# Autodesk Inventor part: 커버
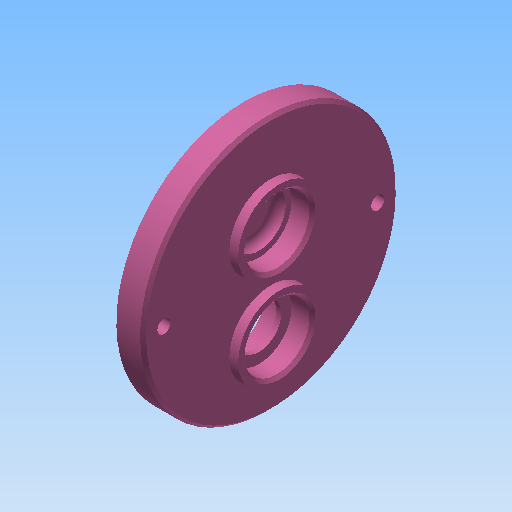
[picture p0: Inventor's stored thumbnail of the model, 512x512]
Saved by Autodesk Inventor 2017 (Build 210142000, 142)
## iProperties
Created: 2016-02
Part Number: 커버
Material: 알루미늄 6061
Document SubType Name: Modeling
Designer: mduedu
Density: 2.71 g/cm^3
Appearance: 분홍색
Author: mduedu
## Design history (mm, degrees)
sketch "스케치1"
  geometry: C1 r 43 at (0, 0); 1 further point
  constraints: 1 centre point, 1 coincident
  dimensions: "d0" = 86 diameter of C1
extrude "돌출1" new body sketch "스케치1" distance "d1" = 9; taper "d2" = 0 deg
sketch "스케치2"
  geometry: C1 r 14 at (0, 11); 1 further point
  constraints: 1 centre point, 1 vertical alignment
  dimensions: "d3" = 28 diameter of C1; "d6" = 11 distance of C1.centre point (0, 0)
extrude "돌출2" join sketch "스케치2" distance "d7" = 3; taper "d8" = 0 deg
sketch "스케치3"
  geometry: C1 r 14 at (0, -20); 1 further point
  constraints: 1 centre point, 1 vertical alignment
  dimensions: "d9" = 28 diameter of C1; "d10" = 20 distance of C1.centre point (0, 0)
extrude "돌출3" join sketch "스케치3" distance "d11" = 3; taper "d12" = 0 deg
hole "구멍1" diameter "d15" = 22; stored, may be unused: countersink angle "d19" = 90 deg, drill point angle "d21" = 0 deg; dims "d13" = 10, "d14" = 10, "d16" = 6, "d17" = 4, "d18" = 2, "d20" = 7
hole "구멍2" diameter "d24" = 18; stored, may be unused: countersink angle "d28" = 90 deg, drill point angle "d30" = 0 deg; dims "d25" = 6, "d26" = 4, "d27" = 2, "d29" = 3, "d95" = 10, "d96" = 10
fillet "모깎기7" dims "d97" = 3
hole "구멍3" diameter "d33" = 22; stored, may be unused: countersink angle "d37" = 90 deg, drill point angle "d39" = 0 deg; dims "d34" = 6, "d35" = 4, "d36" = 2, "d38" = 7, "d73" = 10, "d74" = 10
sketch "스케치4"
  geometry: C1 r 14 at (0, -20) reference; C2 r 18 at (0, -20); 1 further point
  constraints: 1 centre point, 1 coincident
  dimensions: "d40" = 36 diameter of C2
extrude "돌출4" join sketch "스케치4" distance "d41" = 4; taper "d42" = 0 deg
hole "구멍4" diameter "d45" = 22; stored, may be unused: countersink angle "d49" = 90 deg, drill point angle "d51" = 0 deg; dims "d46" = 6, "d47" = 4, "d48" = 2, "d50" = 7.3, "d98" = 10, "d99" = 10
hole "구멍5" diameter "d54" = 15; stored, may be unused: countersink angle "d58" = 90 deg, drill point angle "d60" = 0 deg; dims "d52" = 10, "d53" = 10, "d55" = 6, "d56" = 4, "d57" = 2, "d59" = 7
chamfer "모따기1" distance "d63" = 1; stored, may be unused: second distance "d64" = 2, angle "d65" = 45 deg
chamfer "모따기3" distance "d100" = 0.7; stored, may be unused: second distance "d101" = 2, angle "d102" = 30 deg
sketch "스케치5" dims "d67" = 72
  geometry: 4 further points
  constraints: 2 horizontal alignment, 1 coincident, 5 other
  dimensions: "d71" = 360 deg dimension on point (0, 0) point (-36, 0) (derived)
sketch "스케치6"
  geometry: 2 further points
hole "구멍6" sketch "스케치6" at (-36, 0), (36, 0) diameter "d76" = 4.5; stored, may be unused: countersink angle "d80" = 90 deg, drill point angle "d82" = 0 deg; dims "d77" = 6, "d78" = 8, "d79" = 4.6, "d81" = 8
chamfer "모따기2" distance "d90" = 1; stored, may be unused: second distance "d91" = 2, angle "d92" = 45 deg
node "솔리드1"
